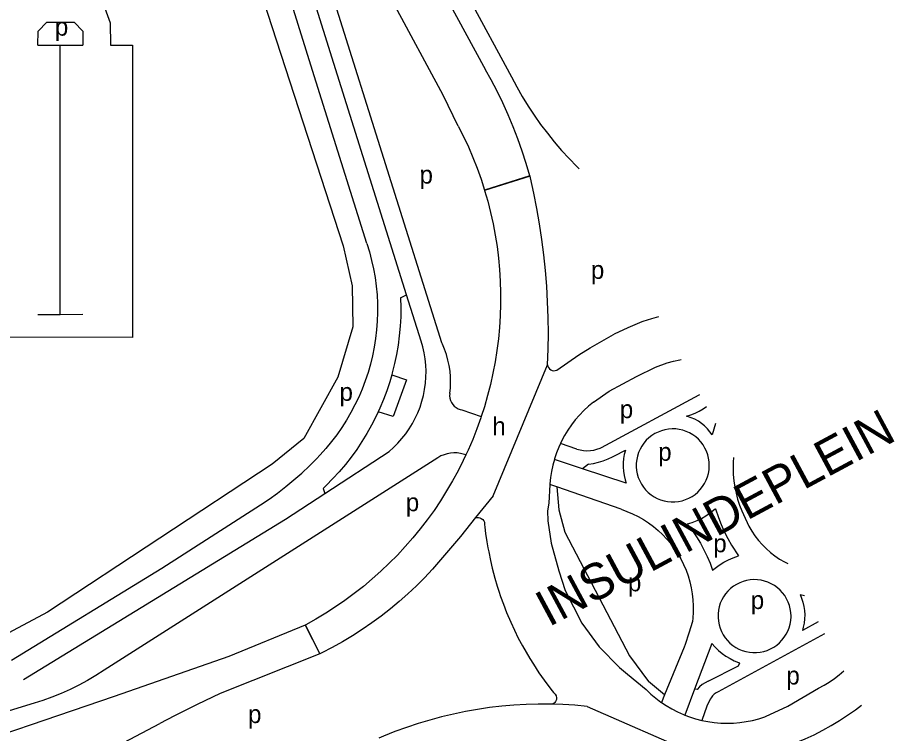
# Model space of a CAD drawing. Extents: x 161494 to 163033, y 383688 to 384862.
# Drawn here: x 162712.5 to 162907.1, y 384182.1 to 384341 of the extents above; entities that cross this region are included whole.
import ezdxf

# ---------------------------------------------------------------- set-up
doc = ezdxf.new("R2010")
doc.units = 0
for name, color, linetype in [('BLT_Basislijn', 7, 'Continuous'), ('BLT_Centroide', 7, 'Continuous'), ('BLT_Straatnaam_hoofdweg', 7, 'Continuous'), ('BLT_Vlakafsluiter', 7, 'Continuous')]:
    doc.layers.add(name, color=color, linetype=linetype)

msp = doc.modelspace()

# ---------------------------------------------------------------- linework, layer by layer
at = {"layer": 'BLT_Basislijn'}
for p, q in [((162790.57, 384376.9), (162816.4, 384329.35)), ((162782.73, 384330.75), (162773.92, 384358.94)), ((162806.45, 384356.92), (162822.17, 384327.78)), ((162806.68, 384268.74), (162781.81, 384347.94)), ((162717.04, 384334.85), (162722.02, 384334.85)), ((162722, 384275), (162722.02, 384334.85)), ((162722.02, 384334.85), (162727, 384334.84)), ((162790.05, 384290.79), (162777.96, 384329.25)), ((162798.86, 384279.46), (162782.73, 384330.75)), ((162797.54, 384278.73), (162798.86, 384279.46)), ((162802.1, 384269.16), (162798.86, 384279.46)), ((162722, 384275), (162717.01, 384274.97)), ((162727, 384275.03), (162722, 384275)), ((162842.1, 384245.55), (162863.79, 384257.23)), ((162811.12, 384253.89), (162815.44, 384252.42)), ((162867.4, 384250.88), (162866.67, 384248.32)), ((162836.68, 384245.2), (162833, 384246.4)), ((162780.71, 384235.32), (162794.98, 384244.64)), ((162844.98, 384243.72), (162847.42, 384244.94)), ((162805.83, 384243.28), (162731.77, 384196.12)), ((162837.92, 384240.83), (162831.66, 384242.89)), ((162839.26, 384241.82), (162837.92, 384240.83)), ((162847.61, 384237.63), (162837.92, 384240.83)), ((162780.33, 384236.44), (162780.71, 384235.32)), ((162832.22, 384236.78), (162830.68, 384237.32)), ((162832.22, 384236.78), (162832.63, 384231.72)), ((162846.49, 384231.82), (162832.22, 384236.78)), ((162744.58, 384218.73), (162766.41, 384232.79)), ((162832.63, 384231.72), (162834, 384226.78)), ((162873.62, 384230.68), (162874.83, 384228.05)), ((162834, 384226.78), (162848.36, 384199.31)), ((162711.22, 384198.35), (162744.58, 384218.73)), ((162886.18, 384212.93), (162887.16, 384212.69)), ((162890.2, 384206.85), (162886.69, 384204.94)), ((162891.6, 384204.16), (162868.04, 384191.32)), ((162860.44, 384201.19), (162856.1, 384190.62)), ((162866.62, 384202.01), (162862.79, 384191.87)), ((162779.6, 384199.74), (162757.47, 384190.96)), ((162848.36, 384199.31), (162852.57, 384193.6)), ((162856.1, 384190.62), (162852.57, 384193.6)), ((162862.79, 384191.87), (162860.63, 384186.15)), ((162863.33, 384191.86), (162862.79, 384191.87)), ((162856.1, 384190.62), (162855.42, 384188.97)), ((162736.15, 384180.03), (162744.08, 384184.32))]:
    msp.add_line(p, q, dxfattribs=at)
for points in [[(162656.92, 384488.75), (162691.6, 384496.32), (162752.47, 384384.97), (162757.12, 384375.47), (162784.76, 384290.27), (162786.79, 384281.41), (162786.93, 384272.34), (162783.57, 384261.18), (162776.08, 384247.54), (162769.02, 384241.88), (162719.16, 384209.03), (162687.54, 384192.14), (162663.49, 384183.13)], [(162777.96, 384329.25), (162763.82, 384374.63), (162726.44, 384443)], [(162810.34, 384316.89), (162806.99, 384323.74), (162784.64, 384365.25)], [(162722.09, 384345.95), (162727.84, 384345.96), (162731.62, 384343.88), (162733.05, 384339.81), (162733.14, 384334.84), (162738.07, 384334.83), (162738.03, 384269.99), (162679.07, 384270.05), (162679.11, 384327.6), (162679.27, 384335.75), (162676.27, 384339.62), (162671.85, 384339.62)], [(162717.04, 384334.85), (162717.07, 384337.98), (162719.06, 384339.98), (162725.07, 384339.97), (162727.05, 384337.98), (162727, 384334.84)], [(162826.24, 384305.82), (162825.43, 384308.58), (162824.54, 384311.33), (162823.57, 384314.04), (162822.52, 384316.73), (162821.41, 384319.39), (162820.22, 384322.01), (162818.95, 384324.61), (162817.62, 384327.16), (162816.4, 384329.35)], [(162822.17, 384327.78), (162823.32, 384325.59), (162824.54, 384323.44), (162825.83, 384321.34), (162827.18, 384319.27), (162828.61, 384317.25), (162830.1, 384315.28), (162831.65, 384313.36), (162833.26, 384311.49), (162834.93, 384309.67), (162836.67, 384307.91), (162837.17, 384307.42)], [(162810.34, 384316.89), (162811.49, 384314.6), (162812.58, 384312.27), (162813.59, 384309.91), (162814.52, 384307.52), (162815.39, 384305.1), (162816.17, 384302.66)], [(162826.26, 384305.77), (162826.24, 384305.82)], [(162830.17, 384263.91), (162830.29, 384267.4), (162830.33, 384270.88), (162830.29, 384274.36), (162830.17, 384277.85), (162829.97, 384281.33), (162829.68, 384284.8), (162829.33, 384288.27), (162828.89, 384291.72), (162828.37, 384295.17), (162827.77, 384298.6), (162827.09, 384302.02), (162826.34, 384305.43), (162826.26, 384305.77)], [(162816.18, 384302.61), (162816.88, 384300.19), (162817.51, 384297.7), (162818.06, 384295.19), (162818.54, 384292.67), (162818.94, 384290.13), (162819.25, 384287.59), (162819.49, 384285.03), (162819.65, 384282.47), (162819.73, 384279.9), (162819.72, 384277.33), (162819.64, 384274.77), (162819.48, 384272.21), (162819.24, 384269.65), (162818.92, 384267.1), (162818.52, 384264.57), (162818.04, 384262.04), (162817.48, 384259.54), (162816.85, 384257.05), (162816.13, 384254.58), (162815.44, 384252.42)], [(162816.17, 384302.66), (162816.18, 384302.61)], [(162790.05, 384290.79), (162790.62, 384288.94), (162791.11, 384287.06), (162791.53, 384285.17), (162791.86, 384283.26), (162792.12, 384281.34), (162792.3, 384279.41), (162792.39, 384277.47), (162792.41, 384275.53), (162792.35, 384273.6), (162792.21, 384271.66), (162791.98, 384269.74), (162791.68, 384267.82), (162791.3, 384265.92), (162790.84, 384264.04), (162790.31, 384262.17), (162789.7, 384260.34), (162789.01, 384258.52), (162788.25, 384256.74), (162787.41, 384254.99), (162786.51, 384253.28), (162785.53, 384251.6), (162784.49, 384249.97), (162783.38, 384248.38), (162782.2, 384246.84), (162780.96, 384245.35), (162779.67, 384243.91), (162779.59, 384243.82)], [(162797.54, 384278.73), (162797.59, 384276.63), (162797.56, 384274.54), (162797.45, 384272.45), (162797.25, 384270.36), (162796.99, 384268.28), (162796.64, 384266.22), (162796.21, 384264.17), (162795.7, 384262.13), (162795.57, 384261.68)], [(162851.06, 384273.46), (162847.96, 384272.1), (162844.94, 384270.68)], [(162854.75, 384274.55), (162853.19, 384274.13), (162851.29, 384273.53), (162851.06, 384273.46)], [(162832.22, 384262.74), (162834.64, 384264.44), (162837.11, 384266.08), (162839.63, 384267.66), (162842.19, 384269.16), (162844.78, 384270.6), (162844.94, 384270.68)], [(162794.98, 384244.64), (162795.99, 384245.54), (162796.95, 384246.5), (162797.84, 384247.51), (162798.68, 384248.57), (162799.45, 384249.68), (162800.16, 384250.84), (162800.8, 384252.03), (162801.36, 384253.26), (162801.85, 384254.52), (162802.27, 384255.81), (162802.61, 384257.12), (162802.87, 384258.45), (162803.05, 384259.79), (162803.15, 384261.14), (162803.18, 384262.49), (162803.12, 384263.84), (162802.98, 384265.19), (162802.77, 384266.52), (162802.47, 384267.85), (162802.1, 384269.16)], [(162808.44, 384257.51), (162808.58, 384258.75), (162808.63, 384260), (162808.6, 384261.25), (162808.5, 384262.5), (162808.31, 384263.74), (162808.05, 384264.96), (162807.71, 384266.17), (162807.29, 384267.35), (162806.8, 384268.5), (162806.68, 384268.74)], [(162856.71, 384264.37), (162858.09, 384264.72), (162859.49, 384264.99), (162859.83, 384265.04)], [(162830.17, 384263.91), (162830.23, 384263.58), (162830.37, 384263.28), (162830.58, 384263.01), (162830.84, 384262.8), (162831.15, 384262.66), (162831.48, 384262.59), (162831.81, 384262.61), (162832.22, 384262.74)], [(162840.36, 384255.57), (162843.8, 384258.05), (162849.88, 384261.33), (162854.08, 384263.38), (162856.71, 384264.37)], [(162795.57, 384261.68), (162795.12, 384260.12), (162794.46, 384258.13), (162793.73, 384256.17), (162792.92, 384254.24), (162792.55, 384253.45)], [(162795.57, 384261.68), (162798.83, 384260.57), (162795.92, 384252.39), (162792.55, 384253.45)], [(162808.44, 384257.51), (162808.42, 384257), (162808.47, 384256.49), (162808.61, 384256), (162808.82, 384255.53), (162809.1, 384255.11), (162809.44, 384254.73), (162809.83, 384254.41), (162810.28, 384254.16), (162810.75, 384253.98), (162811.12, 384253.89)], [(162863.79, 384257.23), (162863.95, 384257.33)], [(162840.36, 384255.57), (162839.27, 384254.68), (162838.23, 384253.73), (162837.24, 384252.72), (162836.31, 384251.66), (162835.45, 384250.54), (162834.65, 384249.38), (162833.91, 384248.17), (162833.25, 384246.93), (162833, 384246.4)], [(162792.55, 384253.45), (162792.04, 384252.34), (162791.08, 384250.48), (162790.06, 384248.65), (162788.96, 384246.86), (162787.81, 384245.12), (162786.58, 384243.42), (162785.29, 384241.77), (162783.93, 384240.17), (162782.52, 384238.63), (162781.05, 384237.14), (162780.33, 384236.44)], [(162861.01, 384252.49), (162861.97, 384252.79), (162862.9, 384253.17), (162863.8, 384253.61), (162864.67, 384254.14), (162865.39, 384254.65)], [(162815.44, 384252.42), (162815.34, 384252.14), (162814.48, 384249.72), (162813.54, 384247.34), (162812.53, 384244.98), (162812.04, 384243.93)], [(162866.67, 384248.32), (162866.18, 384249.04), (162865.62, 384249.71), (162865, 384250.32), (162864.33, 384250.88), (162863.61, 384251.37), (162862.85, 384251.8), (162862.05, 384252.15), (162861.22, 384252.43), (162861.01, 384252.49)], [(162866.05, 384241.57), (162866.01, 384242.38), (162865.89, 384243.17), (162865.69, 384243.95), (162865.41, 384244.71), (162865.07, 384245.43), (162864.65, 384246.12), (162864.16, 384246.77), (162863.62, 384247.36), (162863.02, 384247.89), (162862.36, 384248.36), (162861.67, 384248.77), (162860.93, 384249.1), (162860.17, 384249.36), (162859.39, 384249.55), (162858.59, 384249.65), (162857.79, 384249.67), (162856.98, 384249.62), (162856.19, 384249.48), (162855.41, 384249.27), (162854.66, 384248.98), (162853.94, 384248.62), (162853.26, 384248.19), (162852.63, 384247.69), (162852.05, 384247.14), (162851.53, 384246.52), (162851.07, 384245.86), (162850.68, 384245.16), (162850.36, 384244.42), (162850.11, 384243.65), (162849.94, 384242.87), (162849.85, 384242.07), (162849.84, 384241.26), (162849.92, 384240.46), (162850.07, 384239.67), (162850.29, 384238.9), (162850.6, 384238.15), (162850.97, 384237.44), (162851.42, 384236.77), (162851.92, 384236.15), (162852.49, 384235.58), (162853.11, 384235.06), (162853.78, 384234.62), (162854.49, 384234.24), (162855.24, 384233.93), (162856.01, 384233.7), (162856.8, 384233.55), (162857.6, 384233.48), (162858.41, 384233.48), (162859.21, 384233.57), (162859.99, 384233.73), (162860.76, 384233.98), (162861.5, 384234.29), (162862.21, 384234.68), (162862.87, 384235.14), (162863.48, 384235.66), (162864.04, 384236.24), (162864.54, 384236.87), (162864.98, 384237.55), (162865.34, 384238.27), (162865.63, 384239.02), (162865.85, 384239.79), (162865.99, 384240.58), (162866.04, 384241.39), (162866.05, 384241.57)], [(162833, 384246.4), (162832.65, 384245.65), (162832.13, 384244.34), (162831.69, 384243), (162831.66, 384242.89)], [(162836.68, 384245.2), (162837.4, 384244.99), (162838.15, 384244.87), (162838.9, 384244.82), (162839.65, 384244.85), (162840.39, 384244.96), (162841.12, 384245.15), (162841.82, 384245.42), (162842.1, 384245.55)], [(162766.41, 384232.79), (162768.35, 384234.08), (162770.24, 384235.43), (162772.08, 384236.85), (162773.87, 384238.33), (162775.61, 384239.86), (162777.3, 384241.46), (162778.93, 384243.12), (162779.59, 384243.82)], [(162812.04, 384243.93), (162811.44, 384242.65), (162810.28, 384240.36), (162809.05, 384238.11), (162807.75, 384235.89), (162806.39, 384233.72), (162804.95, 384231.59), (162803.45, 384229.51), (162801.89, 384227.47), (162800.26, 384225.48), (162798.57, 384223.55), (162796.83, 384221.67), (162795.02, 384219.84), (162793.16, 384218.07), (162791.24, 384216.36), (162789.28, 384214.72), (162787.26, 384213.13), (162785.19, 384211.61), (162783.08, 384210.15), (162780.92, 384208.76), (162778.72, 384207.43), (162776.48, 384206.18), (162776.42, 384206.14)], [(162812.04, 384243.93), (162810.84, 384244.23), (162810.11, 384244.33), (162809.37, 384244.36), (162808.62, 384244.3), (162807.89, 384244.16), (162807.18, 384243.95), (162806.5, 384243.66), (162805.83, 384243.28)], [(162839.26, 384241.82), (162840.37, 384242), (162841.46, 384242.27), (162842.52, 384242.6), (162843.57, 384243.02), (162844.58, 384243.5), (162844.98, 384243.72)], [(162847.42, 384244.94), (162847.18, 384244.02), (162847.01, 384243.09), (162846.92, 384242.15), (162846.9, 384241.2), (162846.98, 384240.26), (162847.12, 384239.32), (162847.35, 384238.4), (162847.61, 384237.63)], [(162831.66, 384242.89), (162831.32, 384241.63), (162831.03, 384240.25), (162830.82, 384238.86), (162830.69, 384237.45), (162830.68, 384237.32)], [(162871.44, 384243.3), (162871.36, 384242.29), (162871.32, 384240.91), (162871.36, 384239.52), (162871.49, 384238.14), (162871.69, 384236.76), (162871.97, 384235.4), (162872.33, 384234.06), (162872.76, 384232.74), (162873.27, 384231.45), (162873.62, 384230.68)], [(162830.68, 384237.32), (162830.4, 384233.17), (162830.16, 384231.52), (162830.21, 384229.28), (162830.96, 384224.31), (162832.66, 384218.14)], [(162713.83, 384194.08), (162772.01, 384229.63), (162780.71, 384235.32)], [(162818.1, 384234.83), (162814.19, 384229.97)], [(162846.49, 384231.82), (162847.77, 384231.37), (162849.02, 384230.84), (162850.24, 384230.24), (162851.42, 384229.57), (162852.56, 384228.82), (162853.65, 384228.02), (162854.7, 384227.15), (162855.69, 384226.22), (162856.62, 384225.23), (162857.5, 384224.2), (162858.31, 384223.11), (162859.06, 384221.97), (162859.74, 384220.8), (162860.35, 384219.58), (162860.88, 384218.33), (162861.35, 384217.05), (162861.73, 384215.75), (162862.04, 384214.43), (162862.27, 384213.09), (162862.42, 384211.74), (162862.49, 384210.38), (162862.48, 384209.02), (162862.39, 384207.67), (162862.31, 384206.89)], [(162867.44, 384231.94), (162866.25, 384230.95), (162865.31, 384230.29), (162864.31, 384229.72), (162863.27, 384229.23), (162862.19, 384228.84), (162861.14, 384228.55)], [(162867.44, 384231.94), (162868.06, 384230.04), (162868.67, 384228.45), (162869.37, 384226.89), (162870.13, 384225.36), (162870.96, 384223.87), (162872.52, 384221.48)], [(162814.19, 384229.97), (162810.85, 384225.82), (162804.63, 384218.54)], [(162814.19, 384229.97), (162814.52, 384230.01), (162814.82, 384229.99), (162815.14, 384229.93), (162815.43, 384229.82), (162815.75, 384229.56), (162815.97, 384229.25), (162816.14, 384228.94), (162816.18, 384228.48), (162816.23, 384227.86), (162816.41, 384226.43), (162816.69, 384224.62), (162816.89, 384223.29)], [(162861.14, 384228.55), (162862.29, 384227.05), (162863.21, 384225.7), (162864.07, 384224.3), (162864.85, 384222.86), (162865.57, 384221.38), (162866.21, 384219.87), (162866.79, 384218.28)], [(162874.83, 384228.05), (162875.46, 384226.97), (162876.17, 384225.92), (162876.93, 384224.93), (162877.76, 384223.98), (162878.65, 384223.09), (162879.6, 384222.26), (162880.59, 384221.49), (162881.63, 384220.78), (162882.72, 384220.14), (162883.48, 384219.76)], [(162816.89, 384223.29), (162817.08, 384222.37), (162817.46, 384220.48), (162817.89, 384218.73), (162818.45, 384216.57), (162818.97, 384214.77)], [(162866.79, 384218.28), (162868.26, 384219.41), (162869.24, 384220.06), (162870.28, 384220.62), (162871.36, 384221.09), (162872.52, 384221.48)], [(162804.63, 384218.54), (162802.87, 384216.65), (162801.05, 384214.83), (162799.17, 384213.06), (162797.24, 384211.35), (162795.26, 384209.7), (162793.23, 384208.12), (162791.15, 384206.59), (162789.02, 384205.14), (162786.85, 384203.75), (162784.63, 384202.42), (162782.38, 384201.17), (162780.09, 384199.99), (162779.64, 384199.77)], [(162832.66, 384218.14), (162834.02, 384213.83), (162837.73, 384206.55), (162841.59, 384201.31), (162846.15, 384196.73)], [(162884.18, 384208.11), (162884.14, 384208.92), (162884.02, 384209.71), (162883.82, 384210.49), (162883.55, 384211.25), (162883.2, 384211.98), (162882.78, 384212.66), (162882.3, 384213.3), (162881.75, 384213.9), (162881.15, 384214.43), (162880.49, 384214.9), (162879.8, 384215.31), (162879.07, 384215.64), (162878.31, 384215.9), (162877.52, 384216.09), (162876.72, 384216.19), (162875.92, 384216.21), (162875.12, 384216.16), (162874.32, 384216.02), (162873.55, 384215.81), (162872.8, 384215.52), (162872.08, 384215.16), (162871.4, 384214.73), (162870.76, 384214.23), (162870.18, 384213.68), (162869.66, 384213.06), (162869.2, 384212.4), (162868.81, 384211.7), (162868.49, 384210.96), (162868.24, 384210.19), (162868.08, 384209.41), (162867.99, 384208.61), (162867.98, 384207.8), (162868.05, 384207), (162868.2, 384206.21), (162868.43, 384205.44), (162868.73, 384204.69), (162869.1, 384203.98), (162869.55, 384203.31), (162870.06, 384202.68), (162870.62, 384202.11), (162871.25, 384201.6), (162871.92, 384201.16), (162872.63, 384200.78), (162873.37, 384200.47), (162874.14, 384200.24), (162874.93, 384200.09), (162875.73, 384200.02), (162876.54, 384200.02), (162877.34, 384200.11), (162878.13, 384200.27), (162878.89, 384200.52), (162879.63, 384200.83), (162880.34, 384201.22), (162881, 384201.68), (162881.62, 384202.2), (162882.17, 384202.78), (162882.67, 384203.41), (162883.11, 384204.09), (162883.47, 384204.8), (162883.76, 384205.55), (162883.98, 384206.33), (162884.12, 384207.12), (162884.18, 384207.93), (162884.18, 384208.11)], [(162818.97, 384214.77), (162819.3, 384213.69), (162819.72, 384212.48), (162820.35, 384210.78), (162821.04, 384208.95), (162821.98, 384206.76), (162823.66, 384203.25), (162824.57, 384201.5), (162826.23, 384198.68), (162827.03, 384197.43)], [(162886.18, 384212.93), (162886.54, 384212.07), (162886.83, 384211.19), (162887.04, 384210.28), (162887.17, 384209.36), (162887.22, 384208.43), (162887.19, 384207.5), (162887.08, 384206.57), (162886.9, 384205.66), (162886.69, 384204.94)], [(162862.31, 384206.89), (162861.53, 384204.36), (162860.68, 384201.85), (162860.44, 384201.19)], [(162776.38, 384206.12), (162759.39, 384199.14), (162734, 384190.26), (162693.61, 384176.48), (162646.79, 384161.78), (162617.42, 384153.51)], [(162776.42, 384206.14), (162776.38, 384206.12)], [(162866.62, 384202.01), (162867.32, 384201.23), (162868.07, 384200.5), (162868.88, 384199.83), (162869.74, 384199.22), (162870.64, 384198.69), (162871.57, 384198.22), (162872.55, 384197.82), (162872.82, 384197.73)], [(162779.64, 384199.77), (162779.6, 384199.74)], [(162827.03, 384197.43), (162828.23, 384195.52), (162829.99, 384193.09), (162831.2, 384191.54), (162831.49, 384191.18), (162831.83, 384190.8), (162832.08, 384190.39), (162832.15, 384189.99), (162832.12, 384189.6), (162832.01, 384189.33), (162831.94, 384189.13), (162831.8, 384188.95), (162831.61, 384188.76), (162831.29, 384188.57)], [(162846.15, 384196.73), (162847.86, 384195.23), (162852.06, 384191.8), (162853.09, 384190.82), (162854.18, 384189.9), (162855.32, 384189.04), (162855.42, 384188.97)], [(162865.81, 384193.71), (162872.54, 384197.07), (162872.82, 384197.73)], [(162731.77, 384196.12), (162729.93, 384194.95), (162728.05, 384193.84), (162726.13, 384192.8), (162724.17, 384191.84), (162722.18, 384190.94), (162720.16, 384190.12), (162718.11, 384189.38), (162716.24, 384188.77)], [(162890.29, 384192.11), (162891.5, 384192.76), (162892.67, 384193.48), (162893.8, 384194.26), (162894.89, 384195.11), (162895.87, 384195.97)], [(162865.81, 384193.71), (162865.12, 384193.34), (162864.47, 384192.91), (162863.87, 384192.42), (162863.33, 384191.86)], [(162757.47, 384190.96), (162752.38, 384188.51), (162747.33, 384185.99), (162744.08, 384184.32)], [(162868.04, 384191.32), (162867.56, 384191.08), (162867.13, 384190.77), (162866.75, 384190.41), (162866.43, 384189.98), (162866.24, 384189.66)], [(162878.55, 384185.83), (162883.48, 384188.16), (162890.29, 384192.11)], [(162855.42, 384188.97), (162856.5, 384188.25), (162857.73, 384187.52), (162858.99, 384186.87), (162860.29, 384186.28), (162860.63, 384186.15)], [(162866.24, 384189.66), (162865.51, 384188.1), (162864.38, 384184.98)], [(162716.24, 384188.77), (162674.69, 384176.06), (162634.6, 384163.96)], [(162831.29, 384188.57), (162830.8, 384188.59), (162828.09, 384188.59), (162825.38, 384188.52), (162822.67, 384188.36), (162819.97, 384188.13), (162817.27, 384187.81), (162814.59, 384187.42), (162811.92, 384186.94), (162809.26, 384186.39), (162806.62, 384185.76), (162804, 384185.06), (162801.4, 384184.27), (162798.83, 384183.41), (162796.28, 384182.48), (162793.77, 384181.47), (162792.71, 384181.02)], [(162838.93, 384188.09), (162836.22, 384188.34), (162833.52, 384188.5), (162831.29, 384188.57)], [(162870.78, 384176.39), (162872.91, 384176.68), (162875.03, 384177.05), (162877.14, 384177.5), (162879.23, 384178.02), (162881.3, 384178.63), (162883.34, 384179.3), (162885.35, 384180.06), (162887.34, 384180.89), (162889.3, 384181.79), (162891.21, 384182.77), (162893.1, 384183.81), (162894.94, 384184.93), (162896.74, 384186.11), (162898.49, 384187.35), (162899.83, 384188.38)], [(162860.63, 384186.15), (162861.62, 384185.78), (162862.98, 384185.34), (162864.38, 384184.98)], [(162864.38, 384184.98), (162865.75, 384184.71), (162867.16, 384184.51), (162868.58, 384184.39), (162870, 384184.35), (162871.43, 384184.39), (162872.85, 384184.51), (162874.26, 384184.71), (162875.65, 384184.98), (162877.03, 384185.34), (162878.39, 384185.77), (162878.55, 384185.83)]]:
    msp.add_lwpolyline(points, dxfattribs=at)
at = {"layer": 'BLT_Vlakafsluiter'}
for p, q in [((162826.24, 384305.82), (162816.17, 384302.66)), ((162826.26, 384305.77), (162816.18, 384302.61)), ((162818.1, 384234.83), (162830.17, 384263.91)), ((162776.38, 384206.12), (162779.6, 384199.74)), ((162776.42, 384206.14), (162779.64, 384199.77)), ((162838.93, 384188.09), (162870.21, 384174.43))]:
    msp.add_line(p, q, dxfattribs=at)

# ---------------------------------------------------------------- texts
at = {"layer": 'BLT_Centroide'}
for s, p in [('p', (162720.81, 384336.95)), ('p', (162801.74, 384304.11)), ('p', (162839.77, 384282.97)), ('p', (162783.98, 384255.89)), ('p', (162846.18, 384252.06)), ('h', (162817.89, 384248.28)), ('p', (162854.71, 384242.59)), ('p', (162798.69, 384231.39)), ('p', (162866.93, 384222.29)), ('p', (162847.99, 384213.62)), ('p', (162875.25, 384209.69)), ('p', (162883.15, 384192.94)), ('p', (162763.68, 384184.38))]:
    msp.add_text(s, height=4, dxfattribs=at).set_placement(p)
at = {"layer": 'BLT_Straatnaam_hoofdweg'}
msp.add_text('INSULINDEPLEIN', height=8, rotation=28.2792, dxfattribs=at).set_placement((162830.42, 384205.62))

doc.saveas('drawing.dxf')
